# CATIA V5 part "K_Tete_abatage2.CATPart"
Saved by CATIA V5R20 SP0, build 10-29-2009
Part number: Tete_abatage2
Bounding box of the stored display mesh (mm): x -14 to 14, y 181.692 to 250.868, z 23.968 to 92.671
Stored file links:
  G:\Khaled_CFAO_2011\ST2M\ST2M_GR1\hgrenier\Khaled\CAD_ThinkMOTION\K_Tete_abatage2.CATPart
  C:\Users\Tom\Documents\Cours 2A\CFAO\Projet thinkmotion\Hugo\porte_outil.CATProduct
  G:\Khaled_CFAO_2011\ST2M\ST2M_GR1\hgrenier\Khaled\CAD_ThinkMOTION\K_Squelette.CATPart
  G:\Khaled_CFAO_2011\ST2M\ST2M_GR1\hgrenier\Khaled\CAD_ThinkMOTION\K_Bielette2.CATPart
  G:\Khaled_CFAO_2011\ST2M\ST2M_GR1\hgrenier\Khaled\CAD_ThinkMOTION\K_Tige_verin2.CATPart
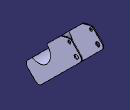
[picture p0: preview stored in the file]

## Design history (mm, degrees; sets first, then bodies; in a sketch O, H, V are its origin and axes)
External parameters (linked from other documents)
  External.Rayon = 2.5697 mm
  External.Rayon.1 = 1.8457 mm
Set1
  Plane1 "plan_sym": linked copy from another document
  Point1 "Centre_verin2/tête": linked copy from another document
  Point2 "Centre_bielette2/tête": linked copy from another document
Body1 (main body)
  Sketch1 on Plane1, origin (0, 0, 0), H (0, 1, 0), V (0, 0, 1)
    arc A1 centre (196.957, 61.9759) radius 15 from (189.2438, 49.111) to (207.3393, 72.8022) ccw
    line L1 (207.3393, 72.8022) -> (225.0977, 90.4164)
    line L2 (225.0977, 90.4164) -> (233.3616, 92.6713)
    line L3 (233.3616, 92.6713) -> (237.7788, 92.6713)
    line L4 (237.7788, 92.6713) -> (252.9473, 77.3786)
    line L5 (252.9473, 77.3786) -> (197.0032, 21.8889)
    line L6 (197.0032, 21.8889) -> (182.4063, 36.6052)
    line L7 (182.4063, 36.6052) -> (182.0488, 37.5223)
    line L8 (183.2439, 43.1598) -> (189.2438, 49.111)
    arc A2 centre (186.9433, 39.4302) radius 5.2532 from (183.2439, 43.1598) to (182.0488, 37.5223) ccw
    radius A1 = 15
    distance L1 L5 = 28.8687
    distance L8 L1 = 4.0772
    radius A2 = 5.2532
    horizontal: L3 H
    perpendicularity: L4 L1
    fix: L5, L4
    parallelism: L8 L5, L6 L4
    tangency: A2 L8, A2 L7
  Pad1: profile Sketch1, direction (1, 0, 0), length 14
  Fillet1: radius 5, on edge [face of Pad1 from Sketch1.L4 | face of Pad1 from Sketch1.L5]; edge [face of Pad1 from Sketch1.L5 | face of Pad1 from Sketch1.L6]
  Shell1: IntOffset 1, Face (start face of Pad1; face of Pad1 from Sketch1.L2; face of Pad1 from Sketch1.L3; face of Pad1 from Sketch1.L1; face of Pad1 from Sketch1.L4), ExtOffset 0
  Sketch2 on end face of Pad1, origin (14, 0, 0), H (0, 1, 0), V (0, 0, 1)
    circle A1 centre (244.422, 77.441) radius 2.5697
    point P1 (244.422, 77.441)
    circle A2 centre (235.708, 89.158) radius 1.8457
    point P2 (235.708, 89.158)
    reference projected point E1 (235.708, 89.158) from Point1
    reference projected point E2 (244.422, 77.441) from Point2
    radius A1 = 2.5697 {= External.Rayon}
    radius A2 = 1.8457 {= External.Rayon.1}
    coincidence: P2 E1, P1 E2
  Pocket1: profile Sketch2, direction (-1, 0, 0), length 1
  Mirror1: of the body so far, about Plane1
